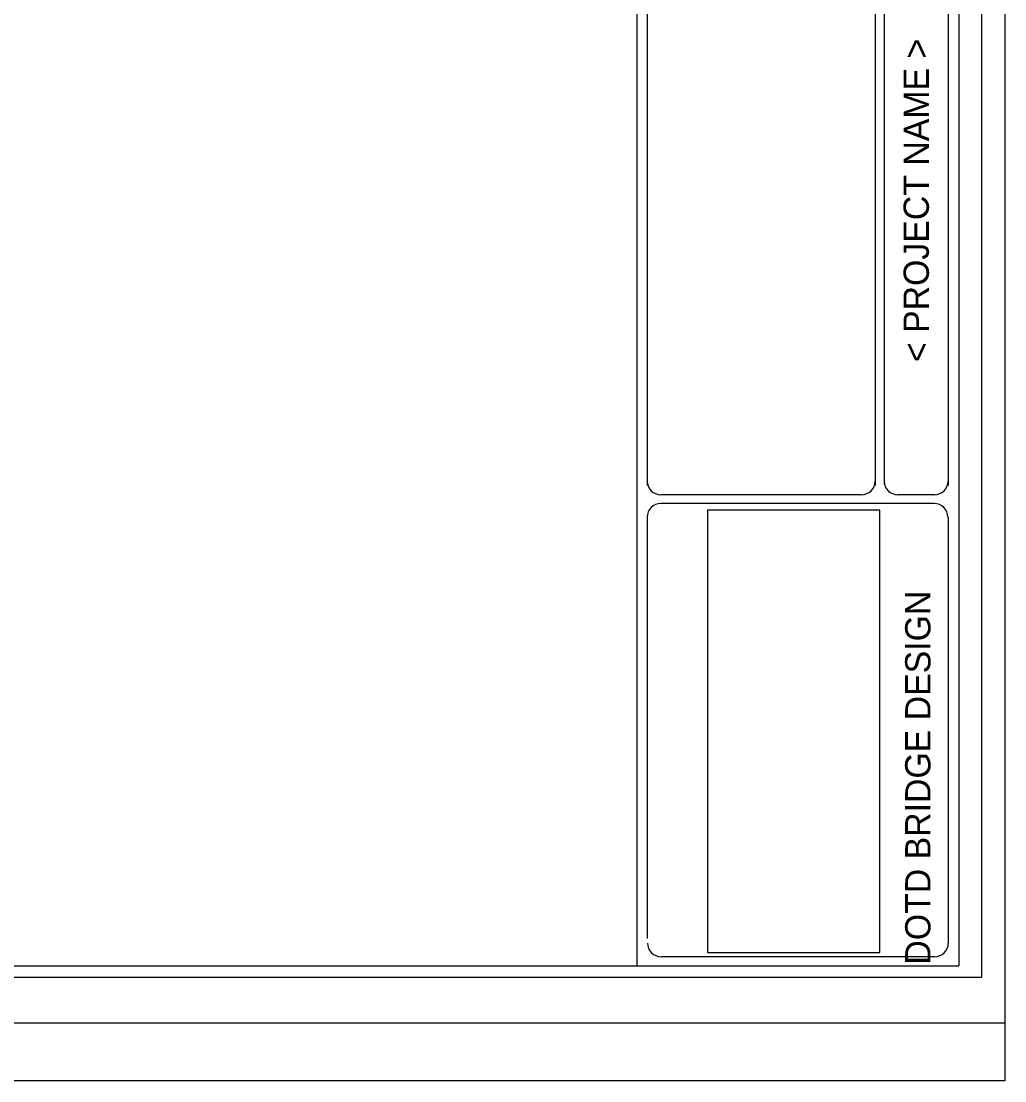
# Model space of a CAD drawing. Extents: x -2.5 to 31.7, y -0.7 to 21.7.
# Drawn here: x 27.423 to 31.7, y -0.5 to 4.108 of the extents above; entities that cross this region are included whole.
import ezdxf

# ---------------------------------------------------------------- set-up
doc = ezdxf.new("R2010")
doc.units = 0
for name, color, linetype in [('Plot Border', 7, 'Continuous'), ('Plot Border 2', 7, 'Continuous'), ('Seal', 7, 'Continuous'), ('Sheet Border', 7, 'Continuous')]:
    doc.layers.add(name, color=color, linetype=linetype)

msp = doc.modelspace()

# ---------------------------------------------------------------- linework, layer by layer
at = {"layer": 'Plot Border'}
for points in [[(-2.3, 21.5), (31.7, 21.5), (31.7, -0.5), (-2.3, -0.5)], [(31.6, 21.05), (-1.4, 21.05), (-1.4, -0.05), (31.6, -0.05)]]:
    msp.add_lwpolyline(points, close=True, dxfattribs=at)
at = {"layer": 'Plot Border 2'}
msp.add_lwpolyline([(-2.3, 21.25), (31.7, 21.25), (31.7, -0.25), (-2.3, -0.25)], close=True, dxfattribs=at)
at = {"layer": 'Seal'}
msp.add_lwpolyline([(31.1572, 0.0577), (31.1572, 1.9809), (30.4079, 1.9809), (30.4079, 0.0577)], close=True, dxfattribs=at)
at = {"layer": 'Sheet Border'}
for p, q in [((30.1, 21), (30.1, 0)), ((31.5, 21), (31.5, 0)), ((30.1458, 6.4486), (30.1458, 2.0926)), ((30.1458, 6.4486), (30.1458, 2.0882)), ((31.1363, 6.4441), (31.1363, 2.0881)), ((31.1759, 6.4486), (31.1759, 2.0926)), ((31.4533, 6.4441), (31.4533, 2.0881)), ((31.0769, 2.0487), (30.2052, 2.0487)), ((31.3939, 2.0487), (31.2354, 2.0487)), ((31.3929, 2.0106), (30.2042, 2.0106)), ((30.1448, 1.9511), (30.1448, 0.1191)), ((31.4543, 1.9511), (31.4543, 0.0991)), ((0, 0), (31.5, 0)), ((31.3949, 0.0396), (30.2057, 0.0396))]:
    msp.add_line(p, q, dxfattribs=at)
for centre, start, end in [((30.205, 2.1082), 180, 270), ((31.0767, 2.1082), 270, 0), ((31.2352, 2.1082), 180, 270), ((31.3937, 2.1082), 270, 0), ((30.2043, 1.9514), 90, 180), ((31.393, 1.9514), 0, 90), ((30.2057, 0.0991), 180, 270), ((31.3949, 0.0991), 270, 360)]:
    msp.add_arc(centre, 0.0594, start, end, dxfattribs=at)

# ---------------------------------------------------------------- texts
for s, p in [('               < PROJECT NAME >               ', (31.3699, 2.0125)), (' DOTD BRIDGE DESIGN', (31.3768, -0.0357))]:
    msp.add_text(s, height=0.11, rotation=90, dxfattribs=at).set_placement(p)

doc.saveas('drawing.dxf')
